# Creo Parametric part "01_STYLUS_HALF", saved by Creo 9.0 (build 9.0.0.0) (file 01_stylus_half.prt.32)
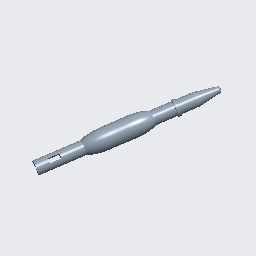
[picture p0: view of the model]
Units: millimeter Newton Second (mmNs); MM, TONNE, SECS

Created from: STYLUS_BOTTOM_V2.PRT

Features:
  1. datum plane "RIGHT"
  2. datum plane "TOP"
  3. datum plane "FRONT"
  4. coordinate system
  5. curve "A_1"
  6. protrusion
  7. cut
  8. datum plane "DTM1"
  9. datum plane "DTM5"
  10. protrusion "Blend 2"
  11. cut
  12. datum plane "DTM2"
  13. cut
  14. datum plane "DTM4"
  15. protrusion
  16. cut
  17. cut
  18. cut
  19. datum plane "DTM3"
  20. revolve "Revolve 1"
  21. extruded cut "Extrude 9"
  22. cut
  23. cut
  24. cut
  25. round
  26. round
  27. round "Round 3"
  28. chamfer "Chamfer 1"
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
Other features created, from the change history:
  protrusion "Blend 2" (2 times)
  revolve "Revolve 2"
  extruded cut "Extrude 10" (2 times)

Other named items: PEN_BODY, NIB_HOLE, SPRING_HOLDER, FORCE_SENSOR, BAT_BODY, BAT_TIP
